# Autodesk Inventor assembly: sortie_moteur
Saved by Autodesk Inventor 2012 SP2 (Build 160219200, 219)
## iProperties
Created: 2013-08
Part Number: sortie_moteur
Document SubType Name: Assembly
Designer: hilarion
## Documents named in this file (3)
- L:\STI2D\Ressources eleves\ITEC\Tsti2d Fichot 2013-14\Webcam motorisee\sortie_moteur.iam
- L:\STI2D\Ressources eleves\ITEC\Tsti2d Fichot 2013-14\Webcam motorisee\Roue dentée Moteur.ipt
- L:\STI2D\Ressources eleves\ITEC\Tsti2d Fichot 2013-14\Webcam motorisee\axe_sortie_moteur.ipt
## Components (2 placed, 2 different names)
1. Roue dentée Moteur:1
2. axe_sortie_moteur:1
